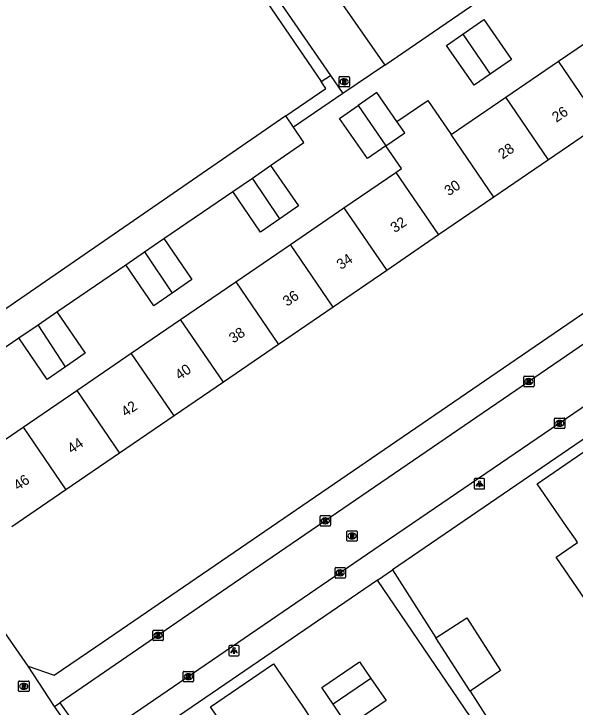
# Model space of a CAD drawing. Extents: x 157466 to 158888, y 383063 to 384677.
# Drawn here: x 158271.4 to 158325.5, y 383594.3 to 383661.2 of the extents above; entities that cross this region are included whole.
import ezdxf

# ---------------------------------------------------------------- set-up
doc = ezdxf.new("R2010")
doc.units = 0
for name, color, linetype in [('IMGEO_Brandkraan', 7, 'Continuous'), ('IMGEO_Groenvoorziening', 7, 'Continuous'), ('IMGEO_Hek', 7, 'Continuous'), ('IMGEO_Kolk', 7, 'Continuous'), ('IMGEO_Lichtpunt', 7, 'Continuous'), ('IMGEO_Pand', 7, 'Continuous'), ('IMGEO_Pand_nummerreeks', 7, 'Continuous'), ('IMGEO_Rijbaan_lokaal_open', 7, 'Continuous'), ('IMGEO_Rioolput', 7, 'Continuous'), ('IMGEO_Voetpad_open', 7, 'Continuous')]:
    doc.layers.add(name, color=color, linetype=linetype)

msp = doc.modelspace()

# ---------------------------------------------------------------- linework, layer by layer
at = {"layer": 'IMGEO_Brandkraan'}
for p, q in [((158271.835, 383595.907), (158271.835, 383596.759)), ((158271.91, 383596.833), (158272.762, 383596.833)), ((158272.323, 383596.613), (158272.348, 383596.613)), ((158272.836, 383596.759), (158272.836, 383595.907)), ((158272.762, 383595.833), (158271.91, 383595.833)), ((158272.346, 383596.053), (158272.321, 383596.053))]:
    msp.add_line(p, q, dxfattribs=at)
for points in [[(158271.835, 383595.907), (158271.835, 383596.759)], [(158271.91, 383596.833), (158272.762, 383596.833)], [(158272.183, 383596.533), (158272.183, 383596.133), (158272.396, 383596.133)], [(158272.414, 383596.533), (158272.183, 383596.533)], [(158272.362, 383596.452), (158272.308, 383596.452), (158272.308, 383596.376)], [(158272.836, 383596.759), (158272.836, 383595.907)], [(158272.762, 383595.833), (158271.91, 383595.833)], [(158272.308, 383596.376), (158272.361, 383596.376)], [(158272.37, 383596.3), (158272.308, 383596.3), (158272.308, 383596.219)], [(158272.308, 383596.219), (158272.37, 383596.219)]]:
    msp.add_lwpolyline(points, dxfattribs=at)
for centre, radius, start, end in [((158271.912, 383596.757), 0.0765, 91.55205, 178.44795), ((158271.912, 383596.757), 0.0765, 91.55205, 178.44795), ((158272.363, 383596.414), 0.0379, 267.82845, 90.93552), ((158272.418, 383596.388), 0.145, 59.4692, 91.53667), ((158272.443, 383596.435), 0.0922, 285.51372, 58.15012), ((158272.76, 383596.757), 0.0765, 1.55205, 88.44795), ((158272.76, 383596.757), 0.0765, 1.55205, 88.44795), ((158271.912, 383595.909), 0.0765, 181.55205, 268.44795), ((158271.912, 383595.909), 0.0765, 181.55205, 268.44795), ((158272.371, 383596.259), 0.0404, 269.87594, 90.50774), ((158272.402, 383596.384), 0.251, 268.66757, 293.53466), ((158272.448, 383596.243), 0.105, 301.31148, 78.98903), ((158272.76, 383595.909), 0.0765, 271.55205, 358.44795), ((158272.76, 383595.909), 0.0765, 271.55205, 358.44795)]:
    msp.add_arc(centre, radius, start, end, dxfattribs=at)
for centre, major_axis, ratio, start_param, end_param in [((158272.322, 383596.333), (-0.387, 0.002), 0.722429, 4.712389, 7.853982), ((158272.347, 383596.333), (-0.39, 0.002), 0.717154, 1.570796, 4.712389)]:
    msp.add_ellipse(centre, major_axis=major_axis, ratio=ratio, start_param=start_param, end_param=end_param, dxfattribs=at)
at = {"layer": 'IMGEO_Groenvoorziening'}
msp.add_lwpolyline([(158301.902, 383655.259), (158303.112, 383653.504), (158298.337, 383650.252)], dxfattribs=at)
at = {"layer": 'IMGEO_Hek'}
for points in [[(158281.192, 383704.728), (158278.101, 383702.589), (158275.89, 383701.379), (158294.448, 383674.456), (158307.144, 383656.25), (158303.112, 383653.504)], [(158307.144, 383656.25), (158344.979, 383682.173), (158341.911, 383686.641)], [(158303.112, 383653.504), (158298.337, 383650.252)], [(158298.337, 383650.252), (158297.608, 383651.339)]]:
    msp.add_lwpolyline(points, dxfattribs=at)
at = {"layer": 'IMGEO_Kolk'}
for p, q in [((158320.544, 383625.302), (158320.544, 383626.154)), ((158320.619, 383626.228), (158321.471, 383626.228)), ((158321.032, 383626.008), (158321.057, 383626.008)), ((158321.545, 383626.154), (158321.545, 383625.302)), ((158321.471, 383625.228), (158320.619, 383625.228)), ((158321.055, 383625.448), (158321.03, 383625.448)), ((158323.516, 383621.273), (158323.516, 383622.125)), ((158323.591, 383622.199), (158324.443, 383622.199)), ((158324.004, 383621.979), (158324.029, 383621.979)), ((158324.517, 383622.125), (158324.517, 383621.273)), ((158324.443, 383621.199), (158323.591, 383621.199)), ((158324.027, 383621.419), (158324.002, 383621.419)), ((158300.913, 383611.864), (158300.913, 383612.716)), ((158300.988, 383612.79), (158301.84, 383612.79)), ((158301.401, 383612.57), (158301.426, 383612.57)), ((158301.914, 383612.716), (158301.914, 383611.864)), ((158301.424, 383612.01), (158301.399, 383612.01)), ((158301.84, 383611.79), (158300.988, 383611.79)), ((158302.352, 383606.848), (158302.352, 383607.7)), ((158302.427, 383607.774), (158303.279, 383607.774)), ((158302.84, 383607.554), (158302.865, 383607.554)), ((158303.353, 383607.7), (158303.353, 383606.848)), ((158303.279, 383606.774), (158302.427, 383606.774)), ((158302.863, 383606.994), (158302.838, 383606.994)), ((158284.779, 383600.813), (158284.779, 383601.665)), ((158284.854, 383601.739), (158285.706, 383601.739)), ((158285.267, 383601.519), (158285.292, 383601.519)), ((158285.78, 383601.665), (158285.78, 383600.813)), ((158285.706, 383600.739), (158284.854, 383600.739)), ((158285.29, 383600.959), (158285.265, 383600.959)), ((158287.709, 383596.843), (158287.709, 383597.695)), ((158287.784, 383597.769), (158288.636, 383597.769)), ((158288.197, 383597.549), (158288.222, 383597.549)), ((158288.71, 383597.695), (158288.71, 383596.843)), ((158288.636, 383596.769), (158287.784, 383596.769)), ((158288.22, 383596.989), (158288.195, 383596.989))]:
    msp.add_line(p, q, dxfattribs=at)
for points in [[(158320.544, 383625.302), (158320.544, 383626.154)], [(158320.619, 383626.228), (158321.471, 383626.228)], [(158320.865, 383625.928), (158320.988, 383625.928), (158320.988, 383625.777), (158321.118, 383625.928), (158321.282, 383625.928), (158321.136, 383625.777), (158321.289, 383625.528), (158321.137, 383625.528), (158321.052, 383625.692), (158320.988, 383625.625), (158320.988, 383625.528), (158320.865, 383625.528), (158320.865, 383625.928)], [(158321.545, 383626.154), (158321.545, 383625.302)], [(158321.471, 383625.228), (158320.619, 383625.228)], [(158323.516, 383621.273), (158323.516, 383622.125)], [(158323.591, 383622.199), (158324.443, 383622.199)], [(158323.837, 383621.899), (158323.96, 383621.899), (158323.96, 383621.748), (158324.09, 383621.899), (158324.254, 383621.899), (158324.108, 383621.748), (158324.261, 383621.499), (158324.109, 383621.499), (158324.024, 383621.663), (158323.96, 383621.596), (158323.96, 383621.499), (158323.837, 383621.499), (158323.837, 383621.899)], [(158324.517, 383622.125), (158324.517, 383621.273)], [(158324.443, 383621.199), (158323.591, 383621.199)], [(158300.913, 383611.864), (158300.913, 383612.716)], [(158300.988, 383612.79), (158301.84, 383612.79)], [(158301.234, 383612.49), (158301.357, 383612.49), (158301.357, 383612.339), (158301.487, 383612.49), (158301.651, 383612.49), (158301.505, 383612.339), (158301.658, 383612.09), (158301.506, 383612.09), (158301.421, 383612.254), (158301.357, 383612.187), (158301.357, 383612.09), (158301.234, 383612.09), (158301.234, 383612.49)], [(158301.914, 383612.716), (158301.914, 383611.864)], [(158301.84, 383611.79), (158300.988, 383611.79)], [(158302.352, 383606.848), (158302.352, 383607.7)], [(158302.427, 383607.774), (158303.279, 383607.774)], [(158302.673, 383607.474), (158302.796, 383607.474), (158302.796, 383607.323), (158302.926, 383607.474), (158303.09, 383607.474), (158302.944, 383607.323), (158303.097, 383607.074), (158302.945, 383607.074), (158302.86, 383607.238), (158302.796, 383607.171), (158302.796, 383607.074), (158302.673, 383607.074), (158302.673, 383607.474)], [(158303.353, 383607.7), (158303.353, 383606.848)], [(158303.279, 383606.774), (158302.427, 383606.774)], [(158284.779, 383600.813), (158284.779, 383601.665)], [(158284.854, 383601.739), (158285.706, 383601.739)], [(158285.1, 383601.439), (158285.223, 383601.439), (158285.223, 383601.288), (158285.353, 383601.439), (158285.517, 383601.439), (158285.371, 383601.288), (158285.524, 383601.039), (158285.372, 383601.039), (158285.287, 383601.203), (158285.223, 383601.136), (158285.223, 383601.039), (158285.1, 383601.039), (158285.1, 383601.439)], [(158285.78, 383601.665), (158285.78, 383600.813)], [(158285.706, 383600.739), (158284.854, 383600.739)], [(158287.709, 383596.843), (158287.709, 383597.695)], [(158287.784, 383597.769), (158288.636, 383597.769)], [(158288.03, 383597.469), (158288.153, 383597.469), (158288.153, 383597.318), (158288.283, 383597.469), (158288.447, 383597.469), (158288.301, 383597.318), (158288.454, 383597.069), (158288.302, 383597.069), (158288.217, 383597.233), (158288.153, 383597.166), (158288.153, 383597.069), (158288.03, 383597.069), (158288.03, 383597.469)], [(158288.71, 383597.695), (158288.71, 383596.843)], [(158288.636, 383596.769), (158287.784, 383596.769)]]:
    msp.add_lwpolyline(points, dxfattribs=at)
for centre, start, end in [((158320.621, 383626.152), 91.55205, 178.44795), ((158320.621, 383626.152), 91.55205, 178.44795), ((158321.469, 383626.152), 1.55205, 88.44795), ((158321.469, 383626.152), 1.55205, 88.44795), ((158320.621, 383625.304), 181.55205, 268.44795), ((158320.621, 383625.304), 181.55205, 268.44795), ((158321.469, 383625.304), 271.55205, 358.44795), ((158321.469, 383625.304), 271.55205, 358.44795), ((158323.593, 383622.123), 91.55205, 178.44795), ((158323.593, 383622.123), 91.55205, 178.44795), ((158324.441, 383622.123), 1.55205, 88.44795), ((158324.441, 383622.123), 1.55205, 88.44795), ((158323.593, 383621.275), 181.55205, 268.44795), ((158323.593, 383621.275), 181.55205, 268.44795), ((158324.441, 383621.275), 271.55205, 358.44795), ((158324.441, 383621.275), 271.55205, 358.44795), ((158300.99, 383612.714), 91.55205, 178.44795), ((158300.99, 383612.714), 91.55205, 178.44795), ((158301.838, 383612.714), 1.55205, 88.44795), ((158301.838, 383612.714), 1.55205, 88.44795), ((158300.99, 383611.866), 181.55205, 268.44795), ((158300.99, 383611.866), 181.55205, 268.44795), ((158301.838, 383611.866), 271.55205, 358.44795), ((158301.838, 383611.866), 271.55205, 358.44795), ((158302.429, 383607.698), 91.55205, 178.44795), ((158302.429, 383607.698), 91.55205, 178.44795), ((158303.277, 383607.698), 1.55205, 88.44795), ((158303.277, 383607.698), 1.55205, 88.44795), ((158302.429, 383606.85), 181.55205, 268.44795), ((158302.429, 383606.85), 181.55205, 268.44795), ((158303.277, 383606.85), 271.55205, 358.44795), ((158303.277, 383606.85), 271.55205, 358.44795), ((158284.856, 383601.663), 91.55205, 178.44795), ((158284.856, 383601.663), 91.55205, 178.44795), ((158285.704, 383601.663), 1.55205, 88.44795), ((158285.704, 383601.663), 1.55205, 88.44795), ((158284.856, 383600.815), 181.55205, 268.44795), ((158284.856, 383600.815), 181.55205, 268.44795), ((158285.704, 383600.815), 271.55205, 358.44795), ((158285.704, 383600.815), 271.55205, 358.44795), ((158287.786, 383597.693), 91.55205, 178.44795), ((158287.786, 383597.693), 91.55205, 178.44795), ((158288.634, 383597.693), 1.55205, 88.44795), ((158288.634, 383597.693), 1.55205, 88.44795), ((158287.786, 383596.845), 181.55205, 268.44795), ((158287.786, 383596.845), 181.55205, 268.44795), ((158288.634, 383596.845), 271.55205, 358.44795), ((158288.634, 383596.845), 271.55205, 358.44795)]:
    msp.add_arc(centre, 0.0765, start, end, dxfattribs=at)
for centre, major_axis, ratio, start_param, end_param in [((158321.031, 383625.728), (-0.387, 0.002), 0.722429, 4.712389, 7.853982), ((158321.056, 383625.728), (-0.39, 0.002), 0.717154, 1.570796, 4.712389), ((158324.003, 383621.699), (-0.387, 0.002), 0.722429, 4.712389, 7.853982), ((158324.028, 383621.699), (-0.39, 0.002), 0.717154, 1.570796, 4.712389), ((158301.4, 383612.29), (-0.387, 0.002), 0.722429, 4.712389, 7.853982), ((158301.425, 383612.29), (-0.39, 0.002), 0.717154, 1.570796, 4.712389), ((158302.839, 383607.274), (-0.387, 0.002), 0.722429, 4.712389, 7.853982), ((158302.864, 383607.274), (-0.39, 0.002), 0.717154, 1.570796, 4.712389), ((158285.266, 383601.239), (-0.387, 0.002), 0.722429, 4.712389, 7.853982), ((158285.291, 383601.239), (-0.39, 0.002), 0.717154, 1.570796, 4.712389), ((158288.196, 383597.269), (-0.387, 0.002), 0.722429, 4.712389, 7.853982), ((158288.221, 383597.269), (-0.39, 0.002), 0.717154, 1.570796, 4.712389)]:
    msp.add_ellipse(centre, major_axis=major_axis, ratio=ratio, start_param=start_param, end_param=end_param, dxfattribs=at)
at = {"layer": 'IMGEO_Lichtpunt'}
for p, q in [((158315.778, 383616.264), (158315.778, 383615.457)), ((158315.778, 383616.264), (158315.778, 383615.457)), ((158316.68, 383616.359), (158315.872, 383616.359)), ((158316.68, 383616.359), (158315.872, 383616.359)), ((158316.774, 383615.457), (158316.774, 383616.264)), ((158316.774, 383615.457), (158316.774, 383616.264)), ((158315.872, 383615.363), (158316.68, 383615.363)), ((158315.872, 383615.363), (158316.68, 383615.363)), ((158292.111, 383600.172), (158292.111, 383599.365)), ((158292.111, 383600.172), (158292.111, 383599.365)), ((158293.013, 383600.267), (158292.205, 383600.267)), ((158293.013, 383600.267), (158292.205, 383600.267)), ((158293.107, 383599.365), (158293.107, 383600.172)), ((158293.107, 383599.365), (158293.107, 383600.172)), ((158292.205, 383599.271), (158293.013, 383599.271)), ((158292.205, 383599.271), (158293.013, 383599.271))]:
    msp.add_line(p, q, dxfattribs=at)
for points in [[(158316.152, 383615.928), (158316.191, 383615.9), (158316.003, 383615.638), (158315.965, 383615.665), (158316.152, 383615.928)], [(158316.254, 383615.88), (158316.301, 383615.88), (158316.301, 383615.558), (158316.254, 383615.558), (158316.254, 383615.88)], [(158316.364, 383615.9), (158316.402, 383615.927), (158316.589, 383615.665), (158316.55, 383615.637), (158316.364, 383615.9)], [(158292.485, 383599.836), (158292.524, 383599.808), (158292.336, 383599.546), (158292.298, 383599.573), (158292.485, 383599.836)], [(158292.587, 383599.788), (158292.634, 383599.788), (158292.634, 383599.466), (158292.587, 383599.466), (158292.587, 383599.788)], [(158292.697, 383599.808), (158292.735, 383599.835), (158292.922, 383599.573), (158292.883, 383599.545), (158292.697, 383599.808)]]:
    msp.add_lwpolyline(points, dxfattribs=at)
for centre in [(158316.277, 383616.062), (158292.61, 383599.97)]:
    msp.add_circle(centre, 0.0994, dxfattribs=at)
for centre, start, end in [((158315.872, 383616.264), 90, 180), ((158315.872, 383616.264), 90, 180), ((158316.68, 383616.264), 0, 90), ((158316.68, 383616.264), 0, 90), ((158315.872, 383615.457), 180, 270), ((158315.872, 383615.457), 180, 270), ((158316.68, 383615.457), 270, 0), ((158316.68, 383615.457), 270, 360), ((158292.205, 383600.172), 90, 180), ((158292.205, 383600.172), 90, 180), ((158293.013, 383600.172), 0, 90), ((158293.013, 383600.172), 0, 90), ((158292.205, 383599.365), 180, 270), ((158292.205, 383599.365), 180, 270), ((158293.013, 383599.365), 270, 0), ((158293.013, 383599.365), 270, 360)]:
    msp.add_arc(centre, 0.0946, start, end, dxfattribs=at)
at = {"layer": 'IMGEO_Pand'}
for points in [[(158248.333, 383658.017), (158282.738, 383681.399), (158301.024, 383654.658)], [(158314.659, 383659.226), (158316.684, 383660.632), (158319.35, 383656.792), (158317.297, 383655.367)], [(158323.89, 383656.617), (158329.194, 383660.242)], [(158317.297, 383655.367), (158315.761, 383654.301), (158313.095, 383658.14), (158314.659, 383659.226)], [(158314.659, 383659.226), (158317.297, 383655.367)], [(158318.815, 383653.147), (158323.89, 383656.617)], [(158328.017, 383650.581), (158323.89, 383656.617)], [(158297.608, 383651.339), (158301.474, 383654), (158301.024, 383654.658)], [(158308.314, 383650.792), (158306.376, 383653.589), (158304.59, 383652.349)], [(158308.314, 383650.792), (158311.304, 383652.836), (158313.551, 383649.549)], [(158313.551, 383649.549), (158318.815, 383653.147)], [(158322.942, 383647.111), (158318.815, 383653.147)], [(158307.251, 383648.456), (158305.481, 383647.227), (158302.793, 383651.1), (158304.59, 383652.349)], [(158304.59, 383652.349), (158307.251, 383648.456)], [(158297.608, 383651.339), (158259.719, 383625.262)], [(158307.251, 383648.456), (158309.064, 383649.715), (158308.314, 383650.792)], [(158328.017, 383650.581), (158322.942, 383647.111)], [(158317.678, 383643.512), (158313.551, 383649.549)], [(158308.211, 383645.899), (158308.748, 383646.266), (158307.251, 383648.456)], [(158322.942, 383647.111), (158317.678, 383643.512)], [(158294.374, 383645.347), (158296.137, 383646.566)], [(158296.137, 383646.566), (158298.829, 383642.666), (158297.04, 383641.431)], [(158292.483, 383644.039), (158294.374, 383645.347)], [(158297.04, 383641.431), (158294.374, 383645.347)], [(158303.209, 383642.479), (158308.211, 383645.899)], [(158308.211, 383645.899), (158312.339, 383639.861)], [(158297.04, 383641.431), (158295.174, 383640.143), (158292.483, 383644.039)], [(158317.678, 383643.512), (158312.339, 383639.861)], [(158298.047, 383638.951), (158303.209, 383642.479)], [(158303.209, 383642.479), (158307.336, 383636.441)], [(158283.969, 383638.226), (158285.823, 383639.506)], [(158285.823, 383639.506), (158288.544, 383635.565), (158286.642, 383634.251)], [(158312.339, 383639.861), (158307.336, 383636.441)], [(158292.778, 383635.349), (158298.047, 383638.951)], [(158302.176, 383632.913), (158298.047, 383638.951)], [(158282.161, 383636.978), (158283.969, 383638.226)], [(158283.969, 383638.226), (158286.642, 383634.251)], [(158286.642, 383634.251), (158284.882, 383633.037), (158282.161, 383636.978)], [(158307.336, 383636.441), (158302.176, 383632.913)], [(158287.461, 383631.714), (158292.778, 383635.349)], [(158292.778, 383635.349), (158296.907, 383629.31)], [(158302.176, 383632.913), (158296.907, 383629.31)], [(158273.721, 383631.207), (158275.535, 383632.452)], [(158275.535, 383632.452), (158278.259, 383628.464), (158276.359, 383627.159)], [(158271.86, 383629.929), (158273.721, 383631.207)], [(158276.359, 383627.159), (158273.721, 383631.207)], [(158282.696, 383628.457), (158287.461, 383631.714)], [(158291.59, 383625.675), (158287.461, 383631.714)], [(158276.359, 383627.159), (158274.579, 383625.937), (158271.86, 383629.929)], [(158296.907, 383629.31), (158291.59, 383625.675)], [(158277.444, 383624.867), (158282.696, 383628.457)], [(158286.825, 383622.417), (158282.696, 383628.457)], [(158291.59, 383625.675), (158286.825, 383622.417)], [(158272.272, 383621.331), (158277.444, 383624.867)], [(158277.444, 383624.867), (158281.574, 383618.826)], [(158286.825, 383622.417), (158281.574, 383618.826)], [(158267.045, 383617.758), (158272.272, 383621.331)], [(158272.272, 383621.331), (158276.402, 383615.29)], [(158325.522, 383610.507), (158324.682, 383611.732), (158321.854, 383615.855), (158327.89, 383619.994), (158331.558, 383614.646)], [(158281.574, 383618.826), (158276.402, 383615.29)], [(158276.402, 383615.29), (158271.175, 383611.716)], [(158329.112, 383605.271), (158328.943, 383605.517), (158326.881, 383604.103), (158323.669, 383608.787), (158325.731, 383610.201), (158325.522, 383610.507)], [(158312.071, 383601.022), (158315.059, 383602.933), (158318.304, 383597.86), (158315.377, 383595.853)], [(158315.377, 383595.853), (158312.071, 383601.022)], [(158293.982, 383589.013), (158290.337, 383594.357), (158296.41, 383598.499), (158299.227, 383594.369), (158300.055, 383593.156)], [(158302.17, 383594.6), (158301.089, 383596.214), (158304.698, 383598.694), (158305.807, 383597.08)], [(158305.807, 383597.08), (158307.269, 383594.953), (158303.615, 383592.442), (158302.17, 383594.6)], [(158305.807, 383597.08), (158302.17, 383594.6)]]:
    msp.add_lwpolyline(points, dxfattribs=at)
at = {"layer": 'IMGEO_Rijbaan_lokaal_open'}
for points in [[(158396.818, 383677.592), (158291.408, 383605.439), (158275.823, 383594.75)], [(158333.171, 383627.939), (158309.83, 383612.03), (158306.706, 383609.901), (158296.72, 383603.094), (158278.623, 383590.71)], [(158275.305, 383594.395), (158275.823, 383594.75)], [(158275.823, 383594.75), (158278.623, 383590.71)], [(158278.116, 383590.363), (158275.305, 383594.395)]]:
    msp.add_lwpolyline(points, dxfattribs=at)
at = {"layer": 'IMGEO_Rioolput'}
for p, q in [((158302.738, 383654.21), (158302.738, 383655.062)), ((158302.813, 383655.136), (158303.665, 383655.136)), ((158303.226, 383654.916), (158303.251, 383654.916)), ((158303.739, 383655.062), (158303.739, 383654.21)), ((158303.665, 383654.136), (158302.813, 383654.136)), ((158303.249, 383654.356), (158303.224, 383654.356)), ((158303.487, 383610.402), (158303.487, 383611.254)), ((158303.562, 383611.328), (158304.414, 383611.328)), ((158304.488, 383611.254), (158304.488, 383610.402)), ((158303.998, 383610.548), (158303.973, 383610.548)), ((158303.975, 383611.108), (158304, 383611.108)), ((158304.414, 383610.328), (158303.562, 383610.328))]:
    msp.add_line(p, q, dxfattribs=at)
for points in [[(158302.738, 383654.21), (158302.738, 383655.062)], [(158302.813, 383655.136), (158303.665, 383655.136)], [(158303.327, 383654.834), (158303.075, 383654.836), (158303.075, 383654.436)], [(158303.253, 383654.755), (158303.199, 383654.755), (158303.199, 383654.674)], [(158303.199, 383654.674), (158303.251, 383654.674)], [(158303.739, 383655.062), (158303.739, 383654.21)], [(158303.665, 383654.136), (158302.813, 383654.136)], [(158303.075, 383654.436), (158303.199, 383654.436), (158303.199, 383654.598), (158303.21, 383654.598)], [(158303.257, 383654.569), (158303.328, 383654.436), (158303.468, 383654.436), (158303.403, 383654.562)], [(158303.487, 383610.402), (158303.487, 383611.254)], [(158303.562, 383611.328), (158304.414, 383611.328)], [(158304.488, 383611.254), (158304.488, 383610.402)], [(158304.076, 383611.026), (158303.824, 383611.028), (158303.824, 383610.628)], [(158303.824, 383610.628), (158303.948, 383610.628), (158303.948, 383610.79), (158303.959, 383610.79)], [(158304.002, 383610.947), (158303.948, 383610.947), (158303.948, 383610.866)], [(158303.948, 383610.866), (158304, 383610.866)], [(158304.006, 383610.761), (158304.077, 383610.628), (158304.217, 383610.628), (158304.152, 383610.754)], [(158304.414, 383610.328), (158303.562, 383610.328)]]:
    msp.add_lwpolyline(points, dxfattribs=at)
for centre, radius, start, end in [((158302.815, 383655.06), 0.0765, 91.55205, 178.44795), ((158302.815, 383655.06), 0.0765, 91.55205, 178.44795), ((158303.235, 383654.863), 0.19, 274.7715, 282.96867), ((158303.259, 383654.659), 0.0964, 77.00612, 93.18647), ((158303.273, 383654.716), 0.0378, 276.66336, 79.67722), ((158303.326, 383654.724), 0.109, 350.36119, 89.41601), ((158303.324, 383654.724), 0.112, 277.58423, 350.98172), ((158303.308, 383654.509), 0.108, 29.51342, 73.79051), ((158303.663, 383655.06), 0.0765, 1.55205, 88.44795), ((158303.663, 383655.06), 0.0765, 1.55205, 88.44795), ((158302.815, 383654.212), 0.0765, 181.55205, 268.44795), ((158302.815, 383654.212), 0.0765, 181.55205, 268.44795), ((158303.209, 383654.545), 0.0533, 26.02933, 88.69889), ((158303.663, 383654.212), 0.0765, 271.55205, 358.44795), ((158303.663, 383654.212), 0.0765, 271.55205, 358.44795), ((158303.564, 383611.252), 0.0765, 91.55205, 178.44795), ((158303.564, 383611.252), 0.0765, 91.55205, 178.44795), ((158304.412, 383611.252), 0.0765, 1.55205, 88.44795), ((158304.412, 383611.252), 0.0765, 1.55205, 88.44795), ((158303.958, 383610.737), 0.0533, 26.02933, 88.69889), ((158303.984, 383611.055), 0.19, 274.7715, 282.96867), ((158304.008, 383610.851), 0.0964, 77.00612, 93.18647), ((158304.022, 383610.908), 0.0378, 276.66336, 79.67722), ((158304.075, 383610.916), 0.109, 350.36119, 89.41601), ((158304.073, 383610.916), 0.112, 277.58423, 350.98172), ((158304.057, 383610.701), 0.108, 29.51342, 73.79051), ((158303.564, 383610.404), 0.0765, 181.55205, 268.44795), ((158303.564, 383610.404), 0.0765, 181.55205, 268.44795), ((158304.412, 383610.404), 0.0765, 271.55205, 358.44795), ((158304.412, 383610.404), 0.0765, 271.55205, 358.44795)]:
    msp.add_arc(centre, radius, start, end, dxfattribs=at)
for centre, major_axis, ratio, start_param, end_param in [((158303.225, 383654.636), (-0.387, 0.002), 0.722429, 4.712389, 7.853982), ((158303.25, 383654.636), (-0.39, 0.002), 0.717154, 1.570796, 4.712389), ((158303.974, 383610.828), (-0.387, 0.002), 0.722429, 4.712389, 7.853982), ((158303.999, 383610.828), (-0.39, 0.002), 0.717154, 1.570796, 4.712389)]:
    msp.add_ellipse(centre, major_axis=major_axis, ratio=ratio, start_param=start_param, end_param=end_param, dxfattribs=at)
at = {"layer": 'IMGEO_Voetpad_open'}
for points in [[(158272.753, 383598.283), (158275.269, 383597.397), (158279.276, 383600.145), (158417.27, 383694.62)], [(158283.135, 383682.466), (158301.902, 383655.259)], [(158301.024, 383654.658), (158301.902, 383655.259)], [(158298.337, 383650.252), (158297.608, 383651.339)], [(158296.137, 383646.566), (158299.353, 383648.768), (158298.337, 383650.252)], [(158285.823, 383639.506), (158292.483, 383644.039)], [(158275.535, 383632.452), (158282.161, 383636.978)], [(158265.202, 383625.393), (158271.86, 383629.929)], [(158334.305, 383625.623), (158307.892, 383607.556)], [(158272.753, 383598.283), (158265.971, 383608.001), (158266.03, 383608.194)], [(158306.438, 383606.562), (158307.892, 383607.556)], [(158307.892, 383607.556), (158312.071, 383601.022)], [(158306.438, 383606.562), (158284.721, 383591.707), (158280.579, 383588.831), (158280.654, 383586.674)], [(158321.177, 383587.078), (158323.081, 383584.275), (158322.051, 383583.576), (158306.438, 383606.562)], [(158275.305, 383594.395), (158272.753, 383598.283)], [(158315.377, 383595.853), (158318.263, 383591.34), (158318.835, 383590.526)]]:
    msp.add_lwpolyline(points, dxfattribs=at)

# ---------------------------------------------------------------- texts
at = {"layer": 'IMGEO_Pand_nummerreeks'}
for s, rotation, p in [('26', 34.36173, (158323.697, 383650.68)), ('28', 34.36173, (158318.507, 383647.132)), ('30', 34.36028, (158313.314, 383643.581)), ('32', 34.36173, (158308.117, 383640.028)), ('34', 34.36173, (158302.926, 383636.478)), ('36', 34.36173, (158297.733, 383632.928)), ('38', 34.36173, (158292.543, 383629.379)), ('40', 34.36173, (158287.351, 383625.829)), ('42', 34.36173, (158282.153, 383622.276)), ('44', 34.36173, (158276.962, 383618.726)), ('46', 34.36173, (158271.769, 383615.176))]:
    msp.add_text(s, height=1, rotation=rotation, dxfattribs=at).set_placement(p)

doc.saveas('drawing.dxf')
